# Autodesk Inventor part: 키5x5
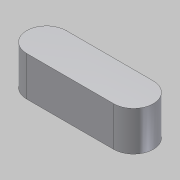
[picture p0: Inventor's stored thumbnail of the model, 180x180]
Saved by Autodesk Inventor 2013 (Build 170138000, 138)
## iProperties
Created: 2013-08
Part Number: 키5x5
Document SubType Name: Modeling
Designer: 한국산업디자인학원
Density: 1 g/cm^3
Material: 일반
Author: 한국산업디자인학원
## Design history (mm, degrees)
sketch "스케치1"
  geometry: L1 (-2.5, -2.5)-(-13.5, -2.5) reference; L2 (-13.5, 2.5)-(-2.5, 2.5) reference; A1 r 2.5 centre (-13.5, 0) between (-13.5, 2.5) and (-13.5, -2.5) reference; A2 r 2.5 centre (-2.5, 0) between (-2.5, -2.5) and (-2.5, 2.5) reference; 1 further point
extrude "돌출1" new body sketch "스케치1" distance "d0" = 5; taper "d1" = 0 deg
node "솔리드1"
node "참조1"
